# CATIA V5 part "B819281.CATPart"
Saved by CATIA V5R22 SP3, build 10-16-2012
Part number: NON BOM-CONN
Revision: -
Definition: B819281
Nomenclature: CHS REQ - NON BOM CONNECTOR
Publications: "Logical Termination.1", "Logical Pin.1", "BCP", "Point.1_generated(BCP)", "XY Plane_generated(BCP)", "CCP", "Z Axis_generated(CCP)", "Y Axis_generated(CCP)", "BaCP"
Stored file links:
  C:\Users\u305772\OneDrive - Gulfstream Aerospace\AD PAG\Harness\B819281.CATPart

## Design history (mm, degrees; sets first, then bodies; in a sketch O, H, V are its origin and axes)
AxisSystem1: origin (0, 0, 0), X (1, 0, 0), Y (0, 1, 0), Z (0, 0, 1)
Set1
  Point1: (0, 0, 0)
Body1 (main body)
